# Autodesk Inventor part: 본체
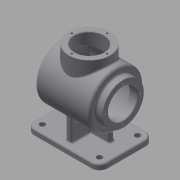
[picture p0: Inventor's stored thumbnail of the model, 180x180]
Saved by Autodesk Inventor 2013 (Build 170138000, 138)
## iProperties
Created: 2016-09
Part Number: 본체
Material: 일반
Document SubType Name: Modeling
Designer: Administrator
Density: 1 g/cm^3
Author: Administrator
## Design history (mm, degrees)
sketch "스케치1"
  geometry: L1 (-67.5, 50)-(67.5, 50); L2 (67.5, 50)-(67.5, -50); L3 (67.5, -50)-(-67.5, -50); L4 (-67.5, -50)-(-67.5, 50); L5 (67.5, -50)-(-67.5, 50); 2 further points
  constraints: 10 end point, 2 parallel, 1 coincident, 1 horizontal, 1 midpoint, 1 perpendicular
  dimensions: "d0" = 135 distance of L1.start L1.end; "d2" = 100 distance of L1.end L2.end
extrude "돌출1" new body sketch "스케치1" distance "d3" = 10; taper "d4" = 0 deg
fillet "모깎기1" dims "d5" = 15
fillet "모깎기2" dims "d6" = 3
hole "구멍1" diameter "d9" = 10; stored, may be unused: countersink angle "d13" = 90 deg, drill point angle "d15" = 0 deg; dims "d7" = 10, "d8" = 10, "d10" = 6, "d11" = 4, "d12" = 2, "d14" = 8
hole "구멍2" diameter "d18" = 10; stored, may be unused: countersink angle "d22" = 90 deg, drill point angle "d24" = 0 deg; dims "d16" = 10, "d17" = 10, "d19" = 6, "d20" = 4, "d21" = 2, "d23" = 8
hole "구멍3" diameter "d27" = 10; stored, may be unused: countersink angle "d31" = 90 deg, drill point angle "d33" = 0 deg; dims "d25" = 10, "d26" = 10, "d28" = 6, "d29" = 4, "d30" = 2, "d32" = 8
hole "구멍4" diameter "d36" = 10; stored, may be unused: countersink angle "d40" = 90 deg, drill point angle "d42" = 0 deg; dims "d34" = 10, "d35" = 10, "d37" = 6, "d38" = 4, "d39" = 2, "d41" = 8
sketch "스케치2"
  geometry: L1 (-52.5, 0)-(52.5, 0) reference; L2 (0, 0)-(0, 82); L3 (-61, 82)-(61, 82); L4 (-61, 82)-(-61, 120); L5 (-61, 120)-(-49, 120); L6 (-49, 120)-(-49, 132); L7 (-49, 132)-(49.562, 132); A1 r 115 centre (-54, 82) between (61, 82) and (49.562, 132)
  constraints: 12 end point, 6 perpendicular, 2 point on circle, 1 centre point, 1 midpoint
  dimensions: "d43" = 82 distance of L2.end L2.start; "d44" = 122 distance of L3.start L3.end; "d45" = 12 distance of L4.end L5.end; "d46" = 110 distance edge to line of A1 L6; "d47" = 115 radius of A1; "d48" = 76 diameter of L5 L3; "d49" = 100 diameter of L7 L3
revolve "회전1" sketch "스케치2" stored, may be unused: angle "d50" = 90 deg
node "작업 평면1"
sketch "스케치3"
  geometry: L1 (61, 38)-(61, -38) reference; L2 (61, 0)-(-1, 0); C1 r 38 at (-1, 0); 1 further point
  constraints: 2 end point, 1 centre point, 1 coincident, 1 midpoint, 1 perpendicular
  dimensions: "d52" = 62 distance of L2.start L2.end; "d54" = 76 diameter of C1
extrude "돌출2" join sketch "스케치3" stored distance "d55" = 10; taper "d56" = 0 deg
sketch "스케치4"
  geometry: L1 (-61, 44)-(-61, 120) reference; L2 (-61, 120)-(-49, 120) reference; L3 (-49, 120)-(-49, 132) reference; L4 (-49, 132)-(-37, 132) reference; L5 (-37, 132)-(-37, 147) reference; L6 (-37, 147)-(39, 147) reference; L7 (39, 147)-(39, 132) reference; L8 (39, 132)-(49.562, 132) reference; L9 (49.562, 32)-(-49, 32) reference; L10 (-49, 32)-(-49, 44) reference; L11 (-49, 44)-(-61, 44) reference; L12 (-67.5, 0)-(-67.5, 7) reference; L13 (-64.5, 10)-(64.5, 10) reference; L14 (67.5, 7)-(67.5, 0) reference; L15 (67.5, 0)-(-67.5, 0) reference; L16 (-61, 82)-(61, 82); L17 (47.661, 129)-(26.333, 129); L18 (-9.833, 129)-(-46, 129); L19 (-46, 129)-(-46, 117); L20 (26.333, 129)-(-9.833, 129); L21 (-46, 117)-(-46, 82); A1 r 115 centre (-54, 82) between (49.562, 32) and (49.562, 132) reference; A2 r 3 centre (-64.5, 7) between (-64.5, 10) and (-67.5, 7) reference; A3 r 3 centre (64.5, 7) between (67.5, 7) and (64.5, 10) reference; A4 r 112 centre (-54, 82) between (58, 82) and (47.661, 129); 1 further point
  constraints: 12 end point, 3 point on circle, 2 collinear, 2 point on line, 1 centre point, 1 midpoint, 1 perpendicular, 1 other
  dimensions: "d57" = 3 radial gap between concentric circles of A1 A4; "d59" = 3 distance between parallel lines of L17 L8
revolve "회전2" sketch "스케치4" stored, may be unused: angle "d60" = 90 deg
hole "구멍5" diameter "d63" = 54; stored, may be unused: countersink angle "d67" = 90 deg, drill point angle "d69" = 0 deg; dims "d61" = 10, "d62" = 10, "d64" = 6, "d65" = 4, "d66" = 2, "d68" = 15
chamfer "모따기1" distance "d70" = 1; stored, may be unused: second distance "d71" = 2, angle "d72" = 45 deg
fillet "모깎기3" dims "d73" = 5
fillet "모깎기4" dims "d74" = 3
fillet "모깎기5" dims "d75" = 3
hole "구멍6" diameter "d78" = 54; stored, may be unused: countersink angle "d82" = 90 deg, drill point angle "d84" = 0 deg; dims "d76" = 10, "d77" = 10, "d79" = 6, "d80" = 4, "d81" = 2, "d83" = 54
chamfer "모따기2" distance "d85" = 1; stored, may be unused: second distance "d86" = 2, angle "d87" = 45 deg
fillet "모깎기6" dims "d88" = 2
sketch "스케치5" dims "d89" = 65
  geometry: L1 (0, 0)-(0, 32.5); C1 r 38 at (0, 0) reference; C2 r 28 at (0, 0) reference; 2 further points
  constraints: 2 coincident, 2 end point, 1 vertical, 1 vertical alignment, 2 other
hole "구멍7" sketch "스케치5" at (0, 32.5) diameter "d91" = 3.242; stored, may be unused: countersink angle "d95" = 90 deg, drill point angle "d97" = 118 deg; dims "d92" = 8, "d93" = 4, "d94" = 2, "d96" = 10
sketch "스케치6" dims "d101" = 65
  geometry: L1 (0, 0)-(0, 32.5); C1 r 38 at (0, 0) reference; C2 r 28 at (0, 0) reference; 2 further points
  constraints: 2 coincident, 2 end point, 1 vertical, 1 vertical alignment, 2 other
hole "구멍8" sketch "스케치6" at (0, 32.5) diameter "d103" = 3.242; stored, may be unused: countersink angle "d107" = 90 deg, drill point angle "d109" = 118 deg; dims "d104" = 8, "d105" = 4, "d106" = 2, "d108" = 10
sketch "스케치7"
  geometry: L1 (-52.5, 50)-(52.5, 50) reference; L2 (67.5, 35)-(67.5, -35) reference; L3 (52.5, -50)-(-52.5, -50) reference; L4 (-67.5, -35)-(-67.5, 35) reference; L5 (0, 50)-(0, -50); L6 (-5, 40)-(5, 40); L7 (5, 40)-(5, -40); L8 (5, -40)-(-5, -40); L9 (-5, -40)-(-5, 40); L10 (5, -40)-(-5, 40); C1 r 5 at (52.5, -35) reference; C2 r 5 at (52.5, 35) reference; C3 r 5 at (-52.5, 35) reference; C4 r 5 at (-52.5, -35) reference; A1 r 15 centre (-52.5, 35) between (-52.5, 50) and (-67.5, 35) reference; A2 r 15 centre (52.5, 35) between (67.5, 35) and (52.5, 50) reference; A3 r 15 centre (52.5, -35) between (52.5, -50) and (67.5, -35) reference; A4 r 15 centre (-52.5, -35) between (-67.5, -35) and (-52.5, -50) reference; 2 further points
  constraints: 12 end point, 4 midpoint, 2 parallel, 1 horizontal, 1 perpendicular, 1 other
  dimensions: "d113" = 10 distance of L6.start L6.end; "d115" = 80 distance of L6.end L7.end
extrude "돌출3" join sketch "스케치7" stored distance "d116" = 10; taper "d117" = 0 deg
sketch "스케치8"
  geometry: L1 (-5, 10)-(-5, 52) reference; L2 (5, 10)-(5, 52) reference; L3 (-52.5, 10)-(52.5, 10) reference; L4 (-94.5, 147)-(94.5, 147) reference; L5 (-44, 32)-(46.374, 32) reference; L6 (-38.075, 32)-(-40, 10); L7 (38.075, 32)-(40, 10); L8 (0, 0)-(0, 24.389); L9 (-52.5, 0)-(52.5, 0) reference; L10 (-67.5, 0)-(-67.5, 7) reference; L11 (67.5, 7)-(67.5, 0) reference
  constraints: 6 end point, 4 point on line, 1 perpendicular
  dimensions: "d118" = 40 distance from line of L6.end L8; "d120" = 95 deg angle of L3 L6; "d122" = 95 deg angle of L7 L3; "d124" = 40 distance from line of L7.end L8
feature "리브1" dims "d125" = 1, "d126" = 10, "d127" = 0, "d128" = 0, "d129" = 1, "d130" = 1
node "작업 평면3"
sketch "스케치9"
  geometry: L1 (-29.035, 4.203)-(29.035, 4.203); L2 (29.035, 4.203)-(29.035, -4.203); L3 (29.035, -4.203)-(-29.035, -4.203); L4 (-29.035, -4.203)-(-29.035, 4.203); L5 (-29.035, -4.203)-(29.035, 4.203); C1 r 47.045 at (0, 0) reference; 2 further points
  constraints: 2 end point, 1 coincident, 1 midpoint, 2 other
feature "엠보싱1" sketch "스케치9" dims "d9" = 10, "d11" = 4, "d12" = 2, "d14" = 8, "d131" = 0.5, "d132" = 0
fillet "모깎기7" dims "d133" = 3
fillet "모깎기8" dims "d134" = 3
fillet "모깎기9" dims "d135" = 3
node "솔리드1"
pattern_circular "원형 패턴1" dims angle "d99" = 360 deg
pattern_circular "원형 패턴2" dims angle "d111" = 360 deg
mirror "대칭1"
node "투영된 루프1"
node "투영된 루프2"
node "투영된 루프3"
node "작업 평면2"
node "투영된 루프4"
node "절단 모서리 투영1"
other parameters: "d51" = 147
